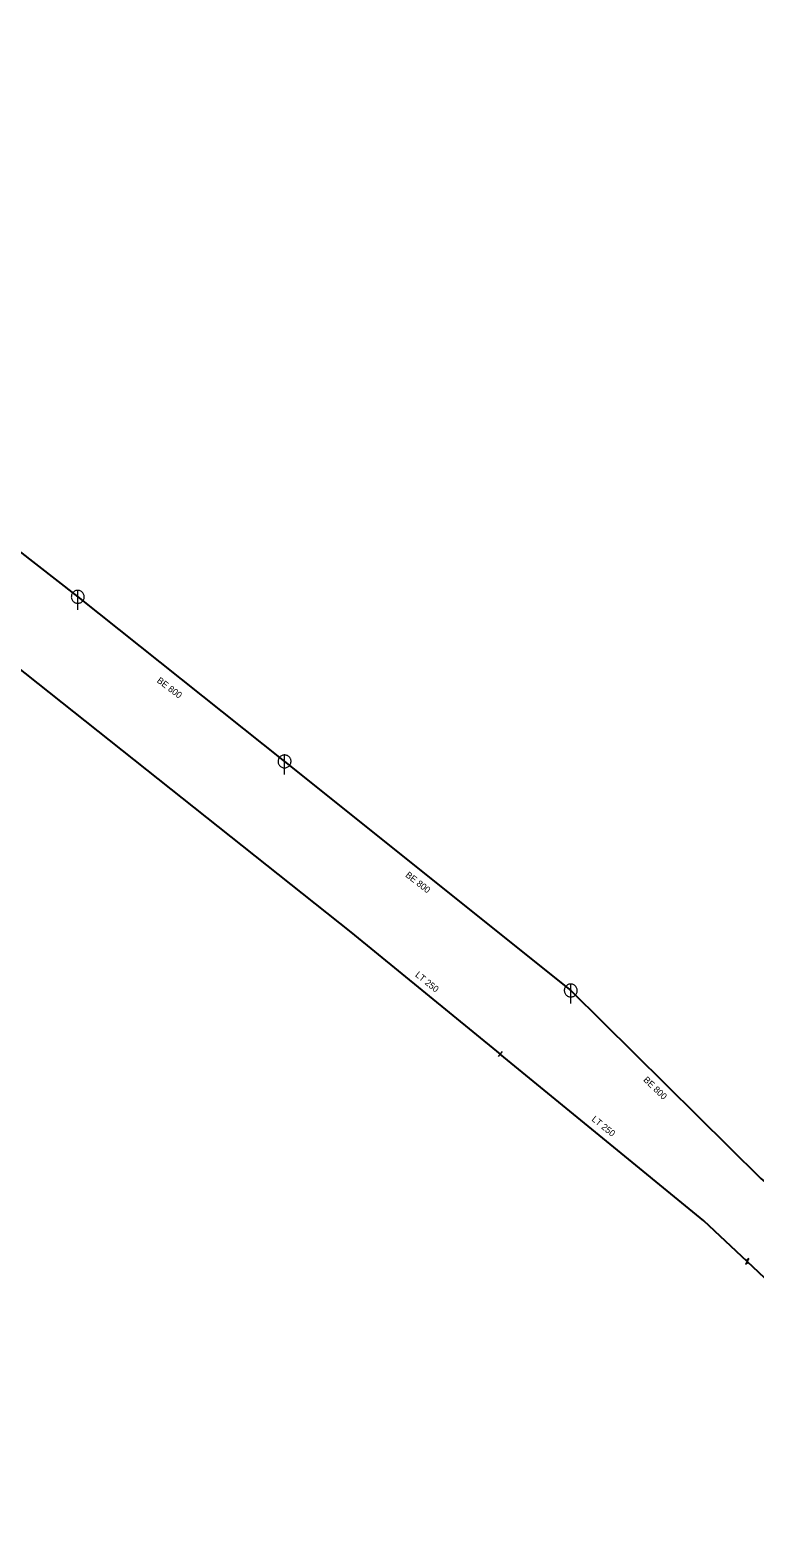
# Model space of a CAD drawing. Extents: x -807203 to -805207, y -993656 to -992505.
# Drawn here: x -806136.1 to -806024, y -993297.8 to -993064.8 of the extents above; entities that cross this region are included whole.
import ezdxf

# ---------------------------------------------------------------- set-up
doc = ezdxf.new("R2010")
doc.units = 0
doc.header["$LTSCALE"] = 0.4
for name, color, linetype, lineweight in [('1', 7, 'Continuous', 13), ('14', 7, 'Continuous', 25), ('17', 7, 'Continuous', 25), ('22', 7, 'Continuous', 13), ('34', 7, 'Continuous', 13), ('47', 7, 'Continuous', 13)]:
    doc.layers.add(name, color=color, linetype=linetype, lineweight=lineweight)

msp = doc.modelspace()

# ---------------------------------------------------------------- linework, layer by layer
at = {"layer": '14'}
for p, q in [((-806173.301, -993117.667), (-806128.75, -993152.399)), ((-806128.75, -993152.399), (-806096.77, -993177.829)), ((-806096.77, -993177.829), (-806052.51, -993213.23))]:
    msp.add_line(p, q, dxfattribs=at)
msp.add_lwpolyline([(-806052.51, -993213.23), (-806023.109, -993242.259), (-806015.82, -993248.39)], dxfattribs=at)
at = {"layer": '17'}
for points in [[(-806260.066, -993064.828), (-806248.392, -993074.528), (-806229.53, -993089.861), (-806208.251, -993107.276), (-806200.433, -993113.675), (-806198.425, -993115.318), (-806170.996, -993137.161), (-806169.414, -993138.403), (-806155.574, -993149.442), (-806086.497, -993204.202), (-806063.424, -993223.055)], [(-806025.237, -993255.101), (-806031.917, -993248.813), (-806048.098, -993235.603), (-806063.424, -993223.055)], [(-805980.27, -993297.811), (-805996.344, -993282.298), (-806025.237, -993255.101)]]:
    msp.add_lwpolyline(points, dxfattribs=at)
at = {"layer": '22'}
for p, q in [((-806128.75, -993154.399), (-806128.749, -993151.399)), ((-806096.77, -993179.829), (-806096.769, -993176.829)), ((-806052.51, -993215.23), (-806052.509, -993212.23))]:
    msp.add_line(p, q, dxfattribs=at)
for points in [[(-806127.75, -993152.399), (-806127.755, -993152.29), (-806127.773, -993152.182), (-806127.803, -993152.076), (-806127.843, -993151.975), (-806127.895, -993151.878), (-806127.957, -993151.788), (-806128.029, -993151.705), (-806128.109, -993151.631), (-806128.197, -993151.565), (-806128.291, -993151.51), (-806128.391, -993151.465), (-806128.496, -993151.432), (-806128.603, -993151.41), (-806128.712, -993151.4), (-806128.822, -993151.402), (-806128.93, -993151.416), (-806129.037, -993151.441), (-806129.14, -993151.478), (-806129.238, -993151.527), (-806129.33, -993151.585), (-806129.416, -993151.654), (-806129.493, -993151.731), (-806129.562, -993151.817), (-806129.621, -993151.909), (-806129.669, -993152.007), (-806129.706, -993152.11), (-806129.732, -993152.217), (-806129.746, -993152.325), (-806129.749, -993152.435), (-806129.739, -993152.544), (-806129.718, -993152.651), (-806129.684, -993152.755), (-806129.64, -993152.855), (-806129.585, -993152.95), (-806129.519, -993153.038), (-806129.445, -993153.118), (-806129.362, -993153.19), (-806129.272, -993153.252), (-806129.176, -993153.304), (-806129.074, -993153.345), (-806128.969, -993153.375), (-806128.861, -993153.393), (-806128.751, -993153.399), (-806128.642, -993153.393), (-806128.534, -993153.375), (-806128.429, -993153.346), (-806128.327, -993153.305), (-806128.23, -993153.253), (-806128.14, -993153.191), (-806128.057, -993153.12), (-806127.982, -993153.04), (-806127.917, -993152.952), (-806127.861, -993152.858), (-806127.817, -993152.758), (-806127.783, -993152.654), (-806127.761, -993152.546), (-806127.751, -993152.437)], [(-806095.77, -993177.829), (-806095.775, -993177.72), (-806095.793, -993177.612), (-806095.823, -993177.506), (-806095.863, -993177.405), (-806095.915, -993177.308), (-806095.977, -993177.218), (-806096.049, -993177.135), (-806096.129, -993177.061), (-806096.217, -993176.995), (-806096.311, -993176.94), (-806096.411, -993176.895), (-806096.516, -993176.862), (-806096.623, -993176.84), (-806096.732, -993176.83), (-806096.842, -993176.832), (-806096.95, -993176.846), (-806097.057, -993176.871), (-806097.16, -993176.908), (-806097.258, -993176.957), (-806097.35, -993177.015), (-806097.436, -993177.084), (-806097.513, -993177.161), (-806097.582, -993177.247), (-806097.641, -993177.339), (-806097.689, -993177.437), (-806097.726, -993177.54), (-806097.752, -993177.647), (-806097.766, -993177.755), (-806097.769, -993177.865), (-806097.759, -993177.974), (-806097.738, -993178.081), (-806097.704, -993178.185), (-806097.66, -993178.285), (-806097.605, -993178.38), (-806097.539, -993178.468), (-806097.465, -993178.548), (-806097.382, -993178.62), (-806097.292, -993178.682), (-806097.196, -993178.734), (-806097.094, -993178.775), (-806096.989, -993178.805), (-806096.881, -993178.823), (-806096.771, -993178.829), (-806096.662, -993178.823), (-806096.554, -993178.805), (-806096.449, -993178.776), (-806096.347, -993178.735), (-806096.25, -993178.683), (-806096.16, -993178.621), (-806096.077, -993178.55), (-806096.002, -993178.47), (-806095.937, -993178.382), (-806095.881, -993178.288), (-806095.837, -993178.188), (-806095.803, -993178.084), (-806095.781, -993177.976), (-806095.771, -993177.867)], [(-806051.51, -993213.23), (-806051.515, -993213.121), (-806051.533, -993213.013), (-806051.563, -993212.907), (-806051.603, -993212.806), (-806051.655, -993212.709), (-806051.717, -993212.619), (-806051.789, -993212.536), (-806051.869, -993212.462), (-806051.957, -993212.396), (-806052.051, -993212.341), (-806052.151, -993212.296), (-806052.256, -993212.263), (-806052.363, -993212.241), (-806052.472, -993212.231), (-806052.582, -993212.233), (-806052.69, -993212.247), (-806052.797, -993212.272), (-806052.9, -993212.309), (-806052.998, -993212.358), (-806053.09, -993212.416), (-806053.176, -993212.485), (-806053.253, -993212.562), (-806053.322, -993212.648), (-806053.381, -993212.74), (-806053.429, -993212.838), (-806053.466, -993212.941), (-806053.492, -993213.048), (-806053.506, -993213.156), (-806053.509, -993213.266), (-806053.499, -993213.375), (-806053.478, -993213.482), (-806053.444, -993213.586), (-806053.4, -993213.686), (-806053.345, -993213.781), (-806053.279, -993213.869), (-806053.205, -993213.949), (-806053.122, -993214.021), (-806053.032, -993214.083), (-806052.936, -993214.135), (-806052.834, -993214.176), (-806052.729, -993214.206), (-806052.621, -993214.224), (-806052.511, -993214.23), (-806052.402, -993214.224), (-806052.294, -993214.206), (-806052.189, -993214.177), (-806052.087, -993214.136), (-806051.99, -993214.084), (-806051.9, -993214.022), (-806051.817, -993213.951), (-806051.742, -993213.871), (-806051.677, -993213.783), (-806051.621, -993213.689), (-806051.577, -993213.589), (-806051.543, -993213.485), (-806051.521, -993213.377), (-806051.511, -993213.268)]]:
    msp.add_lwpolyline(points, close=True, dxfattribs=at)
at = {"layer": '34'}
msp.add_line((-806063.108, -993222.667), (-806063.74, -993223.441), dxfattribs=at)
at = {"layer": '47'}
msp.add_line((-806024.965, -993254.669), (-806025.383, -993254.963), dxfattribs=at)
msp.add_lwpolyline([(-806024.965, -993254.669), (-806025.508, -993255.532), (-806025.09, -993255.238)], dxfattribs=at)

# ---------------------------------------------------------------- texts
at = {"layer": '1'}
for s, rotation, p in [('BE 800', 323, (-806116.609, -993165.524)), ('BE 800', 322, (-806078.168, -993195.558)), ('LT 250', 321, (-806076.659, -993210.966)), ('BE 800', 316, (-806041.37, -993227.134)), ('LT 250', 321, (-806049.369, -993233.272))]:
    msp.add_text(s, height=1, rotation=rotation, dxfattribs=at).set_placement(p)

doc.saveas('drawing.dxf')
